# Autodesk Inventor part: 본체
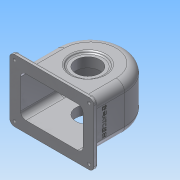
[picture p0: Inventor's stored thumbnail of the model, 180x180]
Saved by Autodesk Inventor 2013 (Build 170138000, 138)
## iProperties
Created: 2016-01
Part Number: 본체
Material: 알루미늄 6061
Document SubType Name: Modeling
Designer: Administrator
Density: 2.71 g/cm^3
Mass: 772.069 g
Surface Area: 1003.9 cm^2
Volume: 284.896 cm^3
Author: Administrator
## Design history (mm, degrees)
sketch "스케치1"
  geometry: L1 (-57, 0)-(-57, -64); L2 (57, 0)-(57, -64); L3 (-57, -64)-(57, -64); C1 r 51 at (0, 0); A1 r 57 centre (0, 0) between (57, 0) and (-57, 0); 1 further point
  constraints: 6 end point, 2 centre point, 2 parallel, 2 point on circle, 2 tangent, 1 coincident, 1 perpendicular, 1 vertical
  dimensions: "d0" = 51 radius of C1; "d1" = 6 radial gap between concentric circles of C1 A1; "d2" = 64 vertical distance of L1.end point (0, 0)
extrude "돌출1" new body sketch "스케치1" stored distance "d3" = 77; taper "d4" = 0 deg
sketch "스케치3"
  geometry: L1 (114, 0)-(114, -77) reference; L2 (0, 0)-(114, 0) reference; L3 (0, 0)-(0, -77) reference; L4 (114, -77)-(0, -77) reference; L5 (-13, -90.5)-(127, -90.5); L6 (127, -90.5)-(127, 13.5); L7 (127, 13.5)-(-13, 13.5); L8 (-13, 13.5)-(-13, -90.5); L9 (-13, -90.5)-(127, 13.5); L10 (127, -90.5)-(-13, 13.5); 1 further point
  constraints: 12 end point, 2 midpoint, 2 parallel, 1 horizontal, 1 perpendicular
  dimensions: "d9" = 140 distance of L7.end L6.end; "d10" = 104 distance of L6.end L5.end
extrude "돌출3" join sketch "스케치3" distance "d11" = 7; taper "d12" = 0 deg
feature "쉘1" dims "d13" = 7, "d14" = 5
sketch "스케치4"
  geometry: L1 (70, -64)-(-70, -64) reference; C1 r 31 at (0, -4); A1 r 57 centre (0, 0) between (57, 0) and (-57, 0) reference
  constraints: 1 centre point, 1 vertical alignment
  dimensions: "d40" = 62 diameter of C1; "d41" = 60 distance from line of L1 C1.centre
extrude "돌출4" join sketch "스케치4" distance "d16" = 10; taper "d17" = 0 deg
hole "구멍3" diameter "d44" = 40; stored, may be unused: countersink angle "d48" = 90 deg, drill point angle "d50" = 0 deg; dims "d42" = 10, "d43" = 10, "d45" = 6, "d46" = 4, "d47" = 2, "d49" = 15
sketch "스케치6"
  geometry: C1 r 20 at (0, 0) reference; 2 further points
  constraints: 1 vertical alignment
  dimensions: "d51" = 24 distance of C1.centre point (0, 24)
hole "구멍4" sketch "스케치6" at (0, 24) diameter "d52" = 2.459; stored, may be unused: countersink angle "d56" = 90 deg, drill point angle "d58" = 0 deg; dims "d53" = 6, "d54" = 4, "d55" = 2, "d57" = 8
fillet "모깎기1" dims "d66" = 14
fillet "모깎기2" dims "d67" = 9
fillet "모깎기3" dims "d68" = 8
node "작업 평면1"
node "작업 평면2"
sketch "스케치11"
  geometry: C1 r 6 at (0, 0); 1 further point
  constraints: 1 centre point, 1 coincident
  dimensions: "d71" = 12 diameter of C1
extrude "돌출5" join sketch "스케치11" stored distance "d72" = 6; taper "d73" = 0 deg
fillet "모깎기4" dims "d74" = 3
hole "구멍5" diameter "d77" = 4.459; stored, may be unused: countersink angle "d81" = 90 deg, drill point angle "d83" = 118 deg; dims "d75" = 10, "d76" = 10, "d78" = 6, "d79" = 4, "d80" = 2, "d82" = 19
sketch "스케치12"
  geometry: A1 r 8 centre (-5, 82.5) between (-5, 90.5) and (-13, 82.5) reference; A2 r 8 centre (-5, -5.5) between (-13, -5.5) and (-5, -13.5) reference; A3 r 8 centre (119, -5.5) between (119, -13.5) and (127, -5.5) reference; A4 r 8 centre (119, 82.5) between (127, 82.5) and (119, 90.5) reference; 5 further points
  constraints: 4 coincident
hole "구멍6" sketch "스케치12" at (-5, 82.5), (-5, -5.5), (119, -5.5), (119, 82.5) diameter "d84" = 5; stored, may be unused: countersink angle "d88" = 90 deg, drill point angle "d90" = 118 deg; dims "d85" = 6, "d86" = 4, "d87" = 2, "d89" = 19
fillet "모깎기5" dims "d91" = 3
fillet "모깎기6" dims "d92" = 1
sketch "스케치13"
  geometry: L1 (0, 0)-(49, 0) reference; L2 (68.5, -64)-(-19.5, -64) reference; 3 further points
  constraints: 1 midpoint, 1 vertical alignment, 1 other
  dimensions: "d93" = 30 distance from line of L2 point (24.5, -34)
feature "엠보싱1" sketch "스케치13" dims "d0" = 51, "d1" = 6, "d2" = 64, "d94" = 0.5, "d95" = 0
node "작업 평면3"
sketch "스케치14"
  geometry: C1 r 28 at (0, 0); 1 further point
  constraints: 1 centre point, 1 coincident
  dimensions: "d97" = 56 diameter of C1
extrude "돌출6" join sketch "스케치14" stored distance "d98" = 10; taper "d99" = 40 deg
node "작업 평면4"
sketch "스케치19"
  geometry: L1 (62, -64)-(-62, -64) reference; C1 r 28 at (0, -4); A1 r 43 centre (0, 0) between (43, 0) and (-43, 0) reference
  constraints: 1 centre point, 1 vertical alignment
  dimensions: "d109" = 56 diameter of C1; "d110" = 60 distance from line of L1 C1.centre
extrude "돌출7" cut sketch "스케치19" distance "d111" = 3; taper "d112" = 0 deg
fillet "모깎기7" dims "d113" = 3
sketch "스케치20"
  geometry: C1 r 25 at (0, 0) reference; 2 further points
  constraints: 1 coincident
hole "구멍7" sketch "스케치20" at (0, 0) diameter "d114" = 40; stored, may be unused: countersink angle "d118" = 90 deg, drill point angle "d120" = 0 deg; dims "d115" = 6, "d116" = 4, "d117" = 2, "d119" = 8
node "솔리드1"
pattern_circular "원형 패턴2" dims angle "d60" = 360 deg
other parameters: "d70" = 6, "d96" = 19.5, "d100" = 35.5
